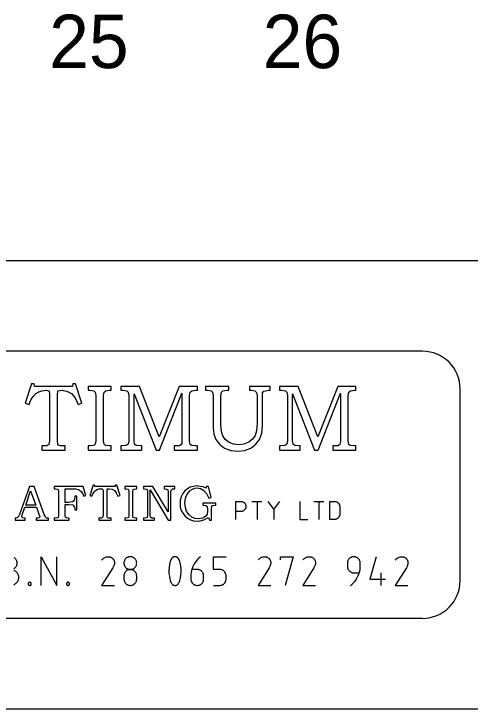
# Model space of a CAD drawing. Extents: x 0 to 841, y 0 to 594.
# Drawn here: x 533.2 to 575.9, y 15 to 80.1 of the extents above; entities that cross this region are included whole.
import ezdxf

# ---------------------------------------------------------------- set-up
doc = ezdxf.new("R2010")
doc.units = 0
for name, color, linetype in [('A1BORDER', 7, 'Continuous'), ('Level 1', 7, 'Continuous'), ('Level 10', 7, 'Continuous')]:
    doc.layers.add(name, color=color, linetype=linetype)

msp = doc.modelspace()

# ---------------------------------------------------------------- linework, layer by layer
at = {"layer": 'A1BORDER'}
for p, q in [((28, 57), (829, 57)), ((829, 15), (28, 15))]:
    msp.add_line(p, q, dxfattribs=at)
at = {"layer": 'Level 1'}
for points in [[(534.66, 35.83), (533.74, 33.23), (533.63, 32.97), (533.53, 32.9), (533.34, 32.87), (533.34, 32.67), (534.27, 32.67), (534.27, 32.87), (534.18, 32.87), (534.03, 32.9), (533.98, 32.93), (533.96, 33.03), (533.98, 33.17), (534.24, 33.9), (535.33, 33.9), (535.56, 33.25), (535.63, 33), (535.6, 32.95), (535.56, 32.9), (535.42, 32.87), (535.3, 32.87), (535.3, 32.67), (536.44, 32.67), (536.44, 32.87), (536.39, 32.87), (536.28, 32.87), (536.2, 32.93), (536.13, 33.05), (536.06, 33.23), (535.12, 35.83)], [(536.99, 35.83), (536.99, 35.63), (537.1, 35.63), (537.28, 35.6), (537.36, 35.55), (537.38, 35.37), (537.38, 33.13), (537.36, 32.95), (537.28, 32.9), (537.08, 32.87), (536.99, 32.87), (536.99, 32.67), (538.4, 32.67), (538.4, 32.87), (538.32, 32.87), (538.13, 32.9), (538.06, 32.97), (538.02, 33.13), (538.02, 34.15), (538.37, 34.15), (538.72, 34.13), (538.87, 33.97), (538.9, 33.87), (538.92, 33.75), (538.92, 33.65), (539.1, 33.65), (539.1, 34.93), (538.92, 34.93), (538.92, 34.85), (538.9, 34.67), (538.87, 34.55), (538.79, 34.45), (538.69, 34.4), (538.34, 34.35), (538.02, 34.35), (538.02, 35.63), (538.72, 35.63), (539.02, 35.63), (539.22, 35.57), (539.37, 35.5), (539.5, 35.37), (539.63, 35.2), (539.76, 34.93), (539.96, 35), (539.69, 35.83)], [(540.64, 35.95), (540.32, 35), (540.52, 34.93), (540.62, 35.15), (540.74, 35.33), (540.87, 35.47), (541, 35.55), (541.17, 35.63), (541.38, 35.63), (541.49, 35.63), (541.53, 35.57), (541.56, 35.45), (541.56, 33.13), (541.52, 32.95), (541.4, 32.87), (541.16, 32.87), (541.16, 32.67), (542.32, 32.67), (542.32, 32.87), (542.08, 32.87), (541.99, 32.9), (541.94, 32.97), (541.94, 33.13), (541.94, 35.43), (541.94, 35.6), (541.97, 35.63), (542.12, 35.63), (542.4, 35.6), (542.63, 35.47), (542.8, 35.25), (542.96, 34.93), (543.16, 35), (542.84, 35.95), (542.7, 35.95), (542.69, 35.83), (540.79, 35.83), (540.77, 35.95)], [(543.59, 35.83), (543.59, 35.63), (543.68, 35.63), (543.87, 35.6), (543.94, 35.55), (543.97, 35.37), (543.97, 33.13), (543.94, 32.95), (543.87, 32.9), (543.68, 32.87), (543.59, 32.87), (543.59, 32.67), (544.74, 32.67), (544.74, 32.87), (544.64, 32.87), (544.47, 32.9), (544.39, 32.95), (544.36, 33.13), (544.36, 35.37), (544.39, 35.55), (544.47, 35.6), (544.64, 35.63), (544.74, 35.63), (544.74, 35.83)], [(545.34, 35.83), (545.34, 35.63), (545.42, 35.63), (545.64, 35.6), (545.72, 35.53), (545.73, 35.37), (545.73, 33.13), (545.69, 32.95), (545.6, 32.9), (545.39, 32.87), (545.34, 32.87), (545.34, 32.67), (546.37, 32.67), (546.37, 32.87), (546.14, 32.87), (546.04, 32.93), (545.99, 32.97), (545.98, 33.13), (545.98, 35.53), (547.66, 32.67), (547.92, 32.67), (547.92, 35.37), (547.96, 35.53), (548.06, 35.63), (548.24, 35.63), (548.29, 35.63), (548.29, 35.83), (547.27, 35.83), (547.27, 35.63), (547.36, 35.63), (547.53, 35.6), (547.62, 35.53), (547.66, 35.37), (547.66, 33.45), (546.23, 35.83)], [(551.26, 35.83), (551.16, 35.67), (550.93, 35.8), (550.64, 35.85), (550.33, 35.9), (550.02, 35.85), (549.73, 35.77), (549.47, 35.63), (549.23, 35.43), (549.03, 35.17), (548.89, 34.87), (548.79, 34.57), (548.77, 34.25), (548.79, 33.9), (548.89, 33.6), (549.03, 33.33), (549.24, 33.07), (549.48, 32.87), (549.74, 32.73), (550.03, 32.63), (550.36, 32.6), (550.67, 32.63), (550.99, 32.73), (551.42, 32.93), (551.54, 32.67), (551.73, 32.67), (551.73, 33.77), (551.76, 33.97), (551.82, 34.05), (552.02, 34.1), (552.12, 34.1), (552.12, 34.27), (550.89, 34.27), (550.89, 34.1), (551.19, 34.05), (551.3, 33.95), (551.34, 33.67), (551.34, 33.53), (551.32, 33.25), (551.19, 33.07), (550.89, 32.87), (550.69, 32.83), (550.48, 32.8), (550.17, 32.85), (549.87, 32.97), (549.6, 33.2), (549.39, 33.53), (549.27, 33.87), (549.22, 34.27), (549.24, 34.55), (549.3, 34.83), (549.4, 35.05), (549.56, 35.27), (549.73, 35.45), (549.93, 35.6), (550.14, 35.67), (550.38, 35.7), (550.7, 35.65), (550.99, 35.47), (551.26, 35.17), (551.48, 34.73), (551.67, 34.8), (551.42, 35.83)], [(534.32, 34.1), (534.78, 35.43), (535.26, 34.1)]]:
    msp.add_lwpolyline(points, close=True, dxfattribs=at)
for points in [[(554, 32.75), (554, 34.44), (554.48, 34.44), (554.52, 34.44), (554.56, 34.43), (554.59, 34.43), (554.64, 34.41), (554.67, 34.39), (554.7, 34.37), (554.74, 34.35), (554.78, 34.33), (554.8, 34.3), (554.83, 34.26), (554.86, 34.24), (554.88, 34.2), (554.9, 34.16), (554.92, 34.13), (554.93, 34.09), (554.94, 34.05), (554.94, 34.01), (554.94, 33.97), (554.94, 33.93), (554.94, 33.89), (554.93, 33.85), (554.92, 33.81), (554.9, 33.77), (554.88, 33.74), (554.86, 33.7), (554.83, 33.67), (554.8, 33.64), (554.78, 33.61), (554.74, 33.59), (554.7, 33.56), (554.67, 33.55), (554.64, 33.53), (554.59, 33.51), (554.56, 33.51), (554.52, 33.5), (554.48, 33.5), (554, 33.5)], [(555.5, 34.44), (556.44, 34.44)], [(555.98, 34.44), (555.98, 32.75)], [(556.99, 34.44), (557.56, 33.69), (558.12, 34.44)], [(559.98, 34.44), (559.98, 32.75), (560.73, 32.75)], [(561.29, 34.44), (562.23, 34.44)], [(561.77, 34.44), (561.77, 32.75)], [(562.78, 32.75), (562.78, 34.44), (563.26, 34.44), (563.29, 34.44), (563.33, 34.43), (563.37, 34.43), (563.42, 34.41), (563.44, 34.39), (563.48, 34.37), (563.52, 34.35), (563.56, 34.33), (563.58, 34.3), (563.6, 34.26), (563.63, 34.24), (563.66, 34.2), (563.68, 34.16), (563.69, 34.13), (563.7, 34.09), (563.72, 34.05), (563.72, 34.01), (563.72, 33.97), (563.72, 33.23), (563.72, 33.17), (563.72, 33.14), (563.7, 33.1), (563.69, 33.06), (563.68, 33.03), (563.66, 32.99), (563.63, 32.95), (563.6, 32.93), (563.58, 32.89), (563.56, 32.86), (563.52, 32.84), (563.48, 32.81), (563.44, 32.8), (563.42, 32.79), (563.37, 32.77), (563.33, 32.76), (563.29, 32.75), (563.26, 32.75), (562.78, 32.75)], [(557.56, 33.69), (557.56, 32.75)], [(533.2, 29.19), (533.26, 29.15), (533.29, 29.13), (533.33, 29.09), (533.37, 29.05), (533.4, 29.01), (533.43, 28.96), (533.46, 28.91), (533.47, 28.86), (533.49, 28.81), (533.49, 28.77), (533.5, 28.71), (533.5, 28.66), (533.5, 28.61), (533.49, 28.56), (533.49, 28.51), (533.47, 28.46), (533.46, 28.41), (533.43, 28.36), (533.4, 28.33), (533.37, 28.27), (533.33, 28.24), (533.29, 28.2), (533.26, 28.17), (533.2, 28.15)], [(535.76, 26.57), (535.76, 29.26), (537.24, 26.57), (537.24, 29.26)], [(541.43, 28.96), (541.48, 29.01), (541.53, 29.07), (541.59, 29.11), (541.67, 29.15), (541.73, 29.19), (541.8, 29.21), (541.88, 29.24), (541.96, 29.25), (542.03, 29.26), (542.07, 29.26), (542.12, 29.26), (542.17, 29.25), (542.22, 29.24), (542.27, 29.23), (542.3, 29.21), (542.36, 29.19), (542.39, 29.16), (542.43, 29.13), (542.47, 29.1), (542.49, 29.05), (542.53, 29.01), (542.56, 28.97), (542.57, 28.94), (542.59, 28.89), (542.6, 28.84), (542.62, 28.79), (542.62, 28.75), (542.62, 28.7), (542.62, 28.66), (542.62, 28.57), (542.59, 28.5), (542.57, 28.43), (542.54, 28.35), (542.5, 28.27), (542.48, 28.21), (541.43, 26.57), (542.62, 26.57)], [(544.12, 28.06), (544.17, 28.06), (544.22, 28.07), (544.27, 28.09), (544.32, 28.1), (544.37, 28.13), (544.42, 28.15), (544.46, 28.17), (544.49, 28.2), (544.53, 28.24), (544.57, 28.27), (544.6, 28.33), (544.63, 28.36), (544.66, 28.41), (544.68, 28.46), (544.69, 28.51), (544.7, 28.56), (544.7, 28.61), (544.72, 28.66), (544.7, 28.71), (544.7, 28.77), (544.69, 28.81), (544.68, 28.86), (544.66, 28.91), (544.63, 28.96), (544.6, 29.01), (544.57, 29.05), (544.53, 29.09), (544.49, 29.13), (544.46, 29.15), (544.42, 29.19), (544.37, 29.2), (544.32, 29.23), (544.27, 29.24), (544.22, 29.25), (544.17, 29.26), (544.12, 29.26), (544.07, 29.26), (544, 29.25), (543.96, 29.24), (543.9, 29.23), (543.86, 29.2), (543.82, 29.19), (543.77, 29.15), (543.73, 29.13), (543.69, 29.09), (543.66, 29.05), (543.62, 29.01), (543.59, 28.96), (543.57, 28.91), (543.56, 28.86), (543.53, 28.81), (543.53, 28.77), (543.52, 28.71), (543.52, 28.66), (543.52, 28.61), (543.53, 28.56), (543.53, 28.51), (543.56, 28.46), (543.57, 28.41), (543.59, 28.36), (543.62, 28.33), (543.66, 28.27), (543.69, 28.24), (543.73, 28.2), (543.77, 28.17), (543.82, 28.15), (543.86, 28.13), (543.9, 28.1), (543.96, 28.09), (544, 28.07), (544.07, 28.06), (544.12, 28.06)], [(548, 26.73), (548.02, 26.7), (548.04, 26.67), (548.07, 26.65), (548.09, 26.64), (548.12, 26.61), (548.16, 26.6), (548.18, 26.59), (548.22, 26.59), (548.24, 26.57), (548.28, 26.57), (548.3, 26.57), (548.34, 26.57), (548.38, 26.57), (548.4, 26.59), (548.43, 26.6), (548.47, 26.61), (548.49, 26.63), (548.52, 26.65), (548.54, 26.66), (548.57, 26.69), (548.59, 26.71), (548.6, 26.73), (548.64, 26.79), (548.69, 26.86), (548.72, 26.94), (548.76, 27.03), (548.82, 27.3), (548.86, 27.57), (548.88, 27.85), (548.87, 28.14), (548.84, 28.41), (548.78, 28.69), (548.76, 28.81), (548.72, 28.9), (548.68, 28.97), (548.64, 29.05), (548.6, 29.11), (548.58, 29.14), (548.56, 29.16), (548.53, 29.19), (548.5, 29.2), (548.48, 29.23), (548.44, 29.24), (548.42, 29.24), (548.38, 29.25), (548.36, 29.26), (548.32, 29.26), (548.29, 29.26), (548.26, 29.26), (548.23, 29.25), (548.19, 29.25), (548.17, 29.24), (548.13, 29.23), (548.1, 29.21), (548.08, 29.19), (548.06, 29.17), (548.03, 29.15), (548, 29.13), (548, 29.11), (547.96, 29.05), (547.9, 28.96), (547.88, 28.89), (547.86, 28.81), (547.78, 28.54), (547.74, 28.26), (547.73, 27.97), (547.73, 27.7), (547.77, 27.43), (547.82, 27.15), (547.86, 27.03), (547.88, 26.94), (547.92, 26.86), (547.96, 26.79), (548, 26.73)], [(550.68, 29.26), (550.53, 29.14), (550.39, 29), (550.27, 28.85), (550.16, 28.7), (550.06, 28.53), (549.97, 28.35), (549.9, 28.16), (549.84, 27.97), (549.8, 27.79), (549.79, 27.6), (549.79, 27.47), (549.79, 27.17), (549.79, 27.13), (549.79, 27.06), (549.8, 27.01), (549.83, 26.96), (549.84, 26.91), (549.87, 26.87), (549.89, 26.83), (549.93, 26.79), (549.97, 26.75), (550, 26.71), (550.04, 26.67), (550.09, 26.65), (550.13, 26.63), (550.18, 26.61), (550.23, 26.59), (550.28, 26.59), (550.33, 26.57), (550.39, 26.57), (550.44, 26.57), (550.49, 26.59), (550.54, 26.59), (550.59, 26.61), (550.64, 26.63), (550.68, 26.65), (550.73, 26.67), (550.77, 26.71), (550.8, 26.75), (550.84, 26.79), (550.88, 26.83), (550.9, 26.87), (550.93, 26.91), (550.94, 26.96), (550.97, 27.01), (550.97, 27.06), (550.98, 27.13), (550.98, 27.17), (550.98, 27.47), (550.98, 27.53), (550.97, 27.57), (550.97, 27.63), (550.94, 27.67), (550.93, 27.73), (550.9, 27.77), (550.88, 27.81), (550.84, 27.85), (550.8, 27.89), (550.77, 27.93), (550.73, 27.96), (550.68, 27.99), (550.64, 28.01), (550.59, 28.03), (550.54, 28.05), (550.49, 28.06), (550.44, 28.06), (550.39, 28.06), (549.94, 28.06)], [(551.89, 26.57), (552.49, 26.57), (552.54, 26.57), (552.59, 26.59), (552.64, 26.59), (552.69, 26.61), (552.74, 26.63), (552.78, 26.65), (552.83, 26.67), (552.87, 26.71), (552.9, 26.75), (552.94, 26.79), (552.98, 26.83), (553, 26.87), (553.03, 26.91), (553.04, 26.96), (553.07, 27.01), (553.07, 27.06), (553.08, 27.13), (553.08, 27.17), (553.08, 27.47), (553.08, 27.53), (553.07, 27.57), (553.07, 27.63), (553.04, 27.67), (553.03, 27.73), (553, 27.77), (552.98, 27.81), (552.94, 27.85), (552.9, 27.89), (552.87, 27.93), (552.83, 27.96), (552.78, 27.99), (552.74, 28.01), (552.69, 28.03), (552.64, 28.05), (552.59, 28.06), (552.54, 28.06), (552.49, 28.06), (551.89, 28.06), (551.89, 29.26), (553.08, 29.26)], [(556.07, 28.96), (556.12, 29.01), (556.17, 29.07), (556.23, 29.11), (556.3, 29.15), (556.37, 29.19), (556.44, 29.21), (556.52, 29.24), (556.59, 29.25), (556.67, 29.26), (556.7, 29.26), (556.76, 29.26), (556.8, 29.25), (556.86, 29.24), (556.9, 29.23), (556.94, 29.21), (556.99, 29.19), (557.03, 29.16), (557.07, 29.13), (557.1, 29.1), (557.13, 29.05), (557.17, 29.01), (557.19, 28.97), (557.2, 28.94), (557.23, 28.89), (557.24, 28.84), (557.26, 28.79), (557.26, 28.75), (557.26, 28.7), (557.26, 28.66), (557.24, 28.57), (557.23, 28.5), (557.2, 28.43), (557.18, 28.35), (557.14, 28.27), (557.1, 28.21), (556.07, 26.57), (557.26, 26.57)], [(558.17, 28.96), (558.17, 29.26), (559.36, 29.26), (558.62, 26.57)], [(560.26, 28.96), (560.3, 29.01), (560.37, 29.07), (560.43, 29.11), (560.49, 29.15), (560.56, 29.19), (560.63, 29.21), (560.7, 29.24), (560.78, 29.25), (560.86, 29.26), (560.89, 29.26), (560.94, 29.26), (560.99, 29.25), (561.04, 29.24), (561.09, 29.23), (561.13, 29.21), (561.18, 29.19), (561.22, 29.16), (561.26, 29.13), (561.29, 29.1), (561.32, 29.05), (561.36, 29.01), (561.38, 28.97), (561.4, 28.94), (561.42, 28.89), (561.43, 28.84), (561.44, 28.79), (561.46, 28.75), (561.46, 28.7), (561.46, 28.66), (561.44, 28.57), (561.42, 28.5), (561.39, 28.43), (561.37, 28.35), (561.33, 28.27), (561.3, 28.21), (560.26, 26.57), (561.46, 26.57)], [(564.74, 26.57), (564.89, 26.7), (565.03, 26.84), (565.16, 26.99), (565.27, 27.14), (565.37, 27.31), (565.46, 27.49), (565.52, 27.66), (565.58, 27.85), (565.62, 28.05), (565.63, 28.24), (565.63, 28.36), (565.63, 28.66), (565.63, 28.71), (565.63, 28.77), (565.62, 28.81), (565.59, 28.86), (565.58, 28.91), (565.56, 28.96), (565.53, 29.01), (565.49, 29.05), (565.46, 29.09), (565.42, 29.13), (565.38, 29.15), (565.34, 29.19), (565.29, 29.2), (565.24, 29.23), (565.19, 29.24), (565.14, 29.25), (565.09, 29.26), (565.04, 29.26), (564.98, 29.26), (564.93, 29.25), (564.88, 29.24), (564.83, 29.23), (564.78, 29.2), (564.74, 29.19), (564.69, 29.15), (564.66, 29.13), (564.62, 29.09), (564.58, 29.05), (564.54, 29.01), (564.52, 28.96), (564.49, 28.91), (564.48, 28.86), (564.46, 28.81), (564.46, 28.77), (564.44, 28.71), (564.44, 28.66), (564.44, 28.36), (564.44, 28.31), (564.46, 28.26), (564.46, 28.21), (564.48, 28.16), (564.49, 28.11), (564.52, 28.06), (564.54, 28.03), (564.58, 27.97), (564.62, 27.94), (564.66, 27.91), (564.69, 27.87), (564.74, 27.85), (564.78, 27.83), (564.83, 27.8), (564.88, 27.79), (564.93, 27.77), (564.98, 27.77), (565.04, 27.77), (565.49, 27.77)], [(567.13, 29.26), (566.53, 27.17), (568.02, 27.17)], [(568.92, 28.96), (568.97, 29.01), (569.02, 29.07), (569.08, 29.11), (569.16, 29.15), (569.22, 29.19), (569.29, 29.21), (569.37, 29.24), (569.44, 29.25), (569.52, 29.26), (569.56, 29.26), (569.6, 29.26), (569.66, 29.25), (569.7, 29.24), (569.76, 29.23), (569.79, 29.21), (569.84, 29.19), (569.88, 29.16), (569.92, 29.13), (569.96, 29.1), (569.98, 29.05), (570.02, 29.01), (570.04, 28.97), (570.06, 28.94), (570.08, 28.89), (570.09, 28.84), (570.1, 28.79), (570.1, 28.75), (570.1, 28.7), (570.1, 28.66), (570.09, 28.57), (570.08, 28.5), (570.06, 28.43), (570.03, 28.35), (569.99, 28.27), (569.96, 28.21), (568.92, 26.57), (570.1, 26.57)], [(533.17, 28.03), (533.23, 28), (533.28, 27.96), (533.34, 27.93), (533.39, 27.89), (533.44, 27.85), (533.48, 27.8), (533.52, 27.75), (533.56, 27.69), (533.59, 27.64), (533.62, 27.57), (533.63, 27.51), (533.64, 27.45), (533.66, 27.39), (533.66, 27.33), (533.66, 27.25), (533.64, 27.19), (533.63, 27.13), (533.62, 27.06), (533.59, 27), (533.56, 26.95), (533.52, 26.89), (533.48, 26.84), (533.44, 26.79), (533.39, 26.75), (533.34, 26.71), (533.28, 26.67), (533.23, 26.64), (533.17, 26.61)], [(543.52, 27.17), (543.52, 27.13), (543.53, 27.06), (543.53, 27.01), (543.56, 26.96), (543.57, 26.91), (543.59, 26.87), (543.62, 26.83), (543.66, 26.79), (543.69, 26.75), (543.73, 26.71), (543.77, 26.67), (543.82, 26.65), (543.86, 26.63), (543.9, 26.61), (543.96, 26.59), (544, 26.59), (544.07, 26.57), (544.12, 26.57), (544.17, 26.57), (544.22, 26.59), (544.27, 26.59), (544.32, 26.61), (544.37, 26.63), (544.42, 26.65), (544.46, 26.67), (544.49, 26.71), (544.53, 26.75), (544.57, 26.79), (544.6, 26.83), (544.63, 26.87), (544.66, 26.91), (544.68, 26.96), (544.69, 27.01), (544.7, 27.06), (544.7, 27.13), (544.72, 27.17), (544.72, 27.47), (544.7, 27.53), (544.7, 27.57), (544.69, 27.63), (544.68, 27.67), (544.66, 27.73), (544.63, 27.77), (544.6, 27.81), (544.57, 27.85), (544.53, 27.89), (544.49, 27.93), (544.46, 27.96), (544.42, 27.99), (544.37, 28.01), (544.32, 28.03), (544.27, 28.05), (544.22, 28.06), (544.17, 28.06), (544.12, 28.06), (544.07, 28.06), (544, 28.06), (543.96, 28.05), (543.9, 28.03), (543.86, 28.01), (543.82, 27.99), (543.77, 27.96), (543.73, 27.93), (543.69, 27.89), (543.66, 27.85), (543.62, 27.81), (543.59, 27.77), (543.57, 27.73), (543.56, 27.67), (543.53, 27.63), (543.53, 27.57), (543.52, 27.53), (543.52, 27.47), (543.52, 27.17)], [(567.58, 27.77), (567.58, 26.57)], [(534.56, 26.73), (534.56, 26.71), (534.56, 26.7), (534.56, 26.69), (534.56, 26.67), (534.57, 26.66), (534.57, 26.65), (534.58, 26.64), (534.58, 26.63), (534.59, 26.61), (534.6, 26.61), (534.62, 26.6), (534.63, 26.59), (534.64, 26.59), (534.64, 26.59), (534.66, 26.57), (534.68, 26.57), (534.69, 26.57), (534.7, 26.57), (534.72, 26.57), (534.73, 26.57), (534.74, 26.57), (534.76, 26.59), (534.77, 26.59), (534.78, 26.59), (534.78, 26.6), (534.79, 26.61), (534.8, 26.61), (534.82, 26.63), (534.82, 26.64), (534.83, 26.65), (534.83, 26.66), (534.84, 26.67), (534.84, 26.69), (534.84, 26.7), (534.84, 26.71), (534.86, 26.73), (534.84, 26.74), (534.84, 26.75), (534.84, 26.76), (534.84, 26.77), (534.83, 26.79), (534.83, 26.8), (534.82, 26.81), (534.82, 26.81), (534.8, 26.83), (534.79, 26.84), (534.78, 26.85), (534.78, 26.85), (534.77, 26.86), (534.76, 26.86), (534.74, 26.86), (534.73, 26.87), (534.72, 26.87), (534.7, 26.87), (534.69, 26.87), (534.68, 26.87), (534.66, 26.86), (534.64, 26.86), (534.64, 26.86), (534.63, 26.85), (534.62, 26.85), (534.6, 26.84), (534.59, 26.83), (534.58, 26.81), (534.58, 26.81), (534.57, 26.8), (534.57, 26.79), (534.56, 26.77), (534.56, 26.76), (534.56, 26.75), (534.56, 26.74), (534.56, 26.73)], [(538.14, 26.73), (538.14, 26.71), (538.14, 26.7), (538.14, 26.69), (538.16, 26.67), (538.16, 26.66), (538.16, 26.65), (538.17, 26.64), (538.17, 26.63), (538.18, 26.61), (538.19, 26.61), (538.2, 26.6), (538.22, 26.59), (538.23, 26.59), (538.24, 26.59), (538.26, 26.57), (538.27, 26.57), (538.28, 26.57), (538.29, 26.57), (538.3, 26.57), (538.32, 26.57), (538.33, 26.57), (538.34, 26.59), (538.36, 26.59), (538.37, 26.59), (538.38, 26.6), (538.38, 26.61), (538.39, 26.61), (538.4, 26.63), (538.4, 26.64), (538.42, 26.65), (538.43, 26.66), (538.43, 26.67), (538.43, 26.69), (538.44, 26.7), (538.44, 26.71), (538.44, 26.73), (538.44, 26.74), (538.44, 26.75), (538.43, 26.76), (538.43, 26.77), (538.43, 26.79), (538.42, 26.8), (538.4, 26.81), (538.4, 26.81), (538.39, 26.83), (538.38, 26.84), (538.38, 26.85), (538.37, 26.85), (538.36, 26.86), (538.34, 26.86), (538.33, 26.86), (538.32, 26.87), (538.3, 26.87), (538.29, 26.87), (538.28, 26.87), (538.27, 26.87), (538.26, 26.86), (538.24, 26.86), (538.23, 26.86), (538.22, 26.85), (538.2, 26.85), (538.19, 26.84), (538.18, 26.83), (538.17, 26.81), (538.17, 26.81), (538.16, 26.8), (538.16, 26.79), (538.16, 26.77), (538.14, 26.76), (538.14, 26.75), (538.14, 26.74), (538.14, 26.73)]]:
    msp.add_lwpolyline(points, dxfattribs=at)
at = {"layer": 'Level 10'}
for p, q in [((571.47, 48.5), (513.54, 48.5)), ((575, 27.03), (575, 44.97)), ((513.54, 23.5), (571.47, 23.5))]:
    msp.add_line(p, q, dxfattribs=at)
for points in [[(534.86, 45.45), (534.26, 43.63), (534.63, 43.5), (534.8, 43.95), (535.03, 44.27), (535.28, 44.55), (535.54, 44.7), (535.84, 44.8), (536.26, 44.85), (536.47, 44.8), (536.53, 44.75), (536.56, 44.5), (536.56, 40.1), (536.5, 39.77), (536.29, 39.65), (535.83, 39.63), (535.83, 39.25), (538.02, 39.25), (538.02, 39.63), (537.56, 39.65), (537.4, 39.7), (537.32, 39.8), (537.29, 40.1), (537.29, 44.43), (537.32, 44.75), (537.37, 44.8), (537.64, 44.85), (538.18, 44.75), (538.6, 44.55), (538.94, 44.13), (539.22, 43.5), (539.59, 43.63), (538.99, 45.45), (538.74, 45.45), (538.7, 45.2), (535.14, 45.2), (535.1, 45.45)], [(540.16, 45.2), (540.16, 44.85), (540.33, 44.85), (540.69, 44.8), (540.83, 44.67), (540.88, 44.35), (540.88, 40.1), (540.83, 39.8), (540.69, 39.67), (540.33, 39.63), (540.16, 39.63), (540.16, 39.25), (542.33, 39.25), (542.33, 39.63), (542.16, 39.63), (541.8, 39.67), (541.66, 39.8), (541.6, 40.1), (541.6, 44.35), (541.66, 44.67), (541.82, 44.8), (542.16, 44.85), (542.33, 44.85), (542.33, 45.2)], [(543.23, 45.2), (543.23, 44.85), (543.43, 44.85), (543.78, 44.8), (543.92, 44.67), (543.98, 44.35), (543.98, 40.1), (543.92, 39.8), (543.74, 39.67), (543.36, 39.63), (543.23, 39.63), (543.23, 39.25), (545.18, 39.25), (545.18, 39.63), (545.06, 39.63), (544.67, 39.67), (544.5, 39.8), (544.46, 40.1), (544.46, 44.5), (546.52, 39.25), (546.86, 39.25), (548.94, 44.57), (548.94, 40.1), (548.93, 39.87), (548.86, 39.73), (548.68, 39.65), (548.38, 39.63), (548.22, 39.63), (548.22, 39.25), (550.39, 39.25), (550.39, 39.63), (550.26, 39.63), (549.87, 39.67), (549.72, 39.77), (549.67, 40.1), (549.67, 44.35), (549.72, 44.67), (549.88, 44.8), (550.26, 44.85), (550.39, 44.85), (550.39, 45.2), (548.68, 45.2), (546.82, 40.5), (544.97, 45.2)], [(551.16, 45.2), (551.16, 44.85), (551.34, 44.85), (551.68, 44.8), (551.82, 44.67), (551.88, 44.35), (551.88, 41.35), (551.93, 40.73), (552.13, 40.23), (552.46, 39.8), (552.94, 39.43), (553.52, 39.2), (554.16, 39.13), (554.8, 39.2), (555.39, 39.43), (555.86, 39.8), (556.2, 40.25), (556.42, 40.83), (556.49, 41.55), (556.49, 44.35), (556.5, 44.6), (556.62, 44.75), (556.79, 44.8), (557.07, 44.85), (557.22, 44.85), (557.22, 45.2), (555.27, 45.2), (555.27, 44.85), (555.43, 44.85), (555.78, 44.8), (555.94, 44.65), (555.99, 44.35), (555.99, 41.73), (555.94, 41.05), (555.82, 40.6), (555.57, 40.27), (555.2, 40), (554.74, 39.8), (554.27, 39.73), (553.78, 39.8), (553.36, 39.97), (553, 40.25), (552.78, 40.57), (552.64, 41), (552.6, 41.65), (552.6, 44.35), (552.64, 44.67), (552.78, 44.8), (553.18, 44.85), (553.33, 44.85), (553.33, 45.2)], [(558.08, 45.2), (558.08, 44.85), (558.28, 44.85), (558.63, 44.8), (558.77, 44.67), (558.82, 44.35), (558.82, 40.1), (558.77, 39.8), (558.59, 39.67), (558.2, 39.63), (558.08, 39.63), (558.08, 39.25), (560.03, 39.25), (560.03, 39.63), (559.9, 39.63), (559.52, 39.67), (559.36, 39.8), (559.3, 40.1), (559.3, 44.5), (561.37, 39.25), (561.7, 39.25), (563.79, 44.57), (563.79, 40.1), (563.77, 39.87), (563.7, 39.73), (563.53, 39.65), (563.23, 39.63), (563.07, 39.63), (563.07, 39.25), (565.24, 39.25), (565.24, 39.63), (565.09, 39.63), (564.7, 39.67), (564.57, 39.77), (564.52, 40.1), (564.52, 44.35), (564.57, 44.67), (564.73, 44.8), (565.09, 44.85), (565.24, 44.85), (565.24, 45.2), (563.53, 45.2), (561.67, 40.5), (559.82, 45.2)]]:
    msp.add_lwpolyline(points, close=True, dxfattribs=at)
for centre, start, end in [((571.465, 44.963), 0, 90), ((571.465, 27.03), 270, 0)]:
    msp.add_arc(centre, 3.535, start, end, dxfattribs=at)

# ---------------------------------------------------------------- texts
at = {"layer": 'Level 1'}
for s, p in [('25', (536.52, 75)), ('26', (556.514, 75))]:
    msp.add_text(s, height=5, dxfattribs=at).set_placement(p)

doc.saveas('drawing.dxf')
